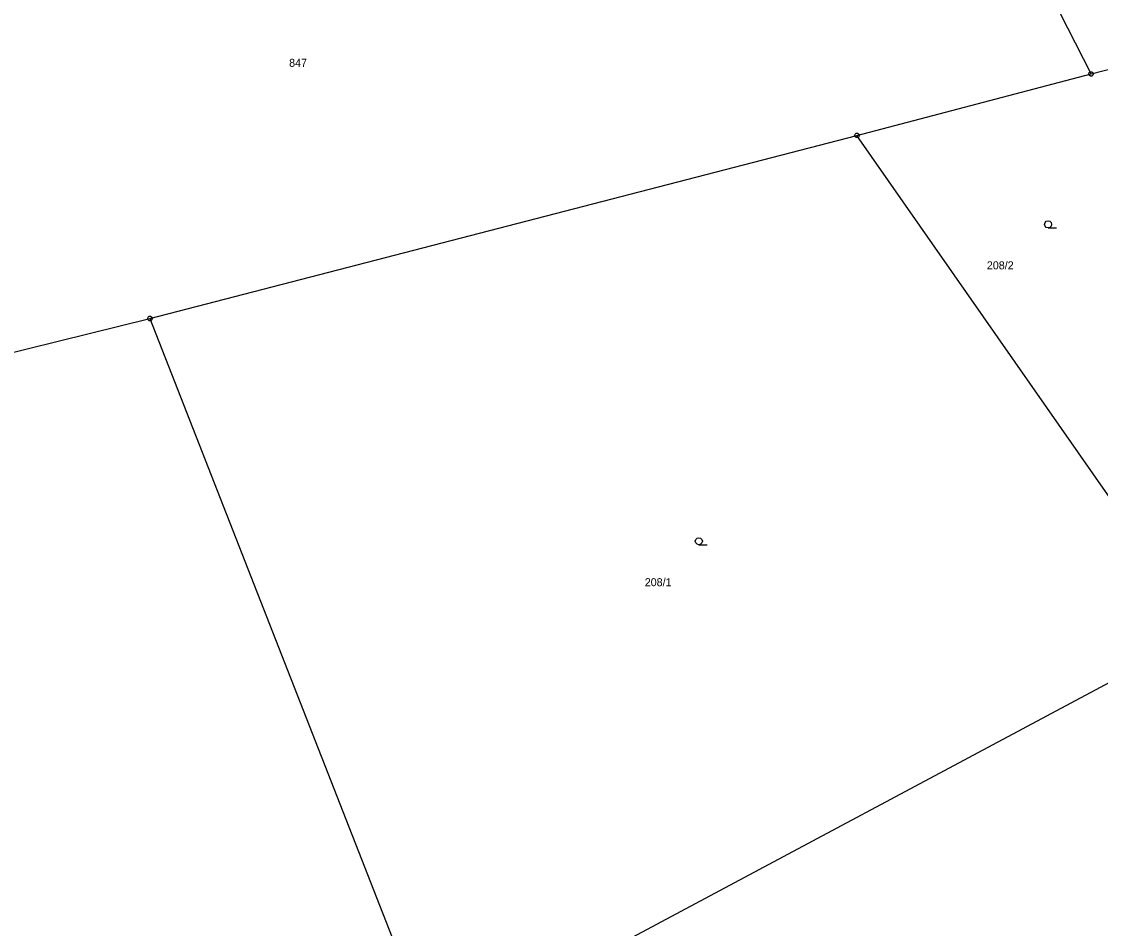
# Model space of a CAD drawing. Extents: x -871430 to -870620, y -1010094 to -1009649.
# Drawn here: x -871095.6 to -871038.3, y -1009905.2 to -1009857 of the extents above; entities that cross this region are included whole.
import ezdxf

# ---------------------------------------------------------------- set-up
doc = ezdxf.new("R2010")
doc.units = 0
for name, color, linetype in [('Vrstva 1', 7, 'Continuous'), ('Vrstva 2', 7, 'Continuous'), ('Vrstva 3', 7, 'Continuous'), ('Vrstva 8', 7, 'Continuous')]:
    doc.layers.add(name, color=color, linetype=linetype)

msp = doc.modelspace()

# ---------------------------------------------------------------- linework, layer by layer
at = {"layer": 'Vrstva 1'}
for p, q in [((-871038.84, -1009859.8), (-871048.58, -1009840.53)), ((-871038.84, -1009859.8), (-871029.61, -1009857.37)), ((-871051.27, -1009863.06), (-871038.84, -1009859.8)), ((-871088.8, -1009872.78), (-871051.27, -1009863.06)), ((-871032.87, -1009889.43), (-871051.27, -1009863.06)), ((-871111.98, -1009878.48), (-871088.8, -1009872.78)), ((-871088.8, -1009872.78), (-871073.74, -1009911.25)), ((-871073.74, -1009911.25), (-871032.87, -1009889.43))]:
    msp.add_line(p, q, dxfattribs=at)
at = {"layer": 'Vrstva 3'}
for points in [[(-871041.12, -1009867.97), (-871041.215, -1009867.945), (-871041.282, -1009867.875), (-871041.308, -1009867.782), (-871041.282, -1009867.69), (-871041.215, -1009867.62), (-871041.12, -1009867.595), (-871041.025, -1009867.62), (-871040.958, -1009867.69), (-871040.932, -1009867.782), (-871040.958, -1009867.875), (-871041.025, -1009867.945), (-871041.12, -1009867.97), (-871040.682, -1009867.97)], [(-871059.66, -1009884.79), (-871059.755, -1009884.765), (-871059.822, -1009884.695), (-871059.848, -1009884.602), (-871059.822, -1009884.51), (-871059.755, -1009884.44), (-871059.66, -1009884.415), (-871059.565, -1009884.44), (-871059.498, -1009884.51), (-871059.472, -1009884.602), (-871059.498, -1009884.695), (-871059.565, -1009884.765), (-871059.66, -1009884.79), (-871059.222, -1009884.79)]]:
    msp.add_lwpolyline(points, dxfattribs=at)
at = {"layer": 'Vrstva 8'}
for p, q in [((-871038.852, -1009859.8), (-871038.828, -1009859.8)), ((-871051.282, -1009863.06), (-871051.258, -1009863.06)), ((-871088.812, -1009872.78), (-871088.788, -1009872.78))]:
    msp.add_line(p, q, dxfattribs=at)
for points in [[(-871038.802, -1009859.68), (-871038.74, -1009859.728), (-871038.715, -1009859.8), (-871038.74, -1009859.872), (-871038.802, -1009859.92), (-871038.878, -1009859.92), (-871038.94, -1009859.872), (-871038.965, -1009859.8), (-871038.94, -1009859.728), (-871038.878, -1009859.68), (-871038.802, -1009859.68)], [(-871051.232, -1009862.94), (-871051.17, -1009862.988), (-871051.145, -1009863.06), (-871051.17, -1009863.133), (-871051.232, -1009863.18), (-871051.308, -1009863.18), (-871051.37, -1009863.133), (-871051.395, -1009863.06), (-871051.37, -1009862.988), (-871051.308, -1009862.94), (-871051.232, -1009862.94)], [(-871088.763, -1009872.66), (-871088.7, -1009872.708), (-871088.675, -1009872.78), (-871088.7, -1009872.852), (-871088.763, -1009872.9), (-871088.838, -1009872.9), (-871088.9, -1009872.852), (-871088.925, -1009872.78), (-871088.9, -1009872.708), (-871088.838, -1009872.66), (-871088.763, -1009872.66)]]:
    msp.add_lwpolyline(points, dxfattribs=at)

# ---------------------------------------------------------------- texts
at = {"layer": 'Vrstva 2'}
for s, p in [('847', (-871081.409, -1009859.422)), ('208/2', (-871044.371, -1009870.17)), ('208/1', (-871062.531, -1009886.99))]:
    msp.add_text(s, height=0.425, dxfattribs=at).set_placement(p)

doc.saveas('drawing.dxf')
